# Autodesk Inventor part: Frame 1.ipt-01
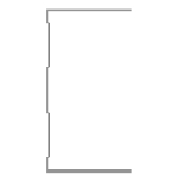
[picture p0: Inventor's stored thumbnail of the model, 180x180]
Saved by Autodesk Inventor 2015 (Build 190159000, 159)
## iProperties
Created: 2015-04
Part Number: Frame 1.ipt-01
Material: Aluminum 6061
Description: Kévin Novo
Document SubType Name: Modeling
Standard: Kevin
Designer: suporte
Standards Organization: Kevin
Language: en-US
Size Designation: (Unnamed 1)
Categories: <MemberInstance><Categories><Category DisplayName="Structural Shapes" InternalName="089c4875-fa83-4c05-b084-43b9cc11f5ed" Mnemonic="GRDR"><CategoryParameter Dis
Density: 2.7 g/cm^3
Appearance: Aluminum - Flat
IsCustomPart: 1
_CCFamilyMember: 1
_CCFamilyDisplayName: Kévin - Kévin Novo
_FrameMemberDoc: Frame Member File
_Version: 15.0.0
_GetPNFromCC: 1
Author: suporte
G_L: 1275,000 mm
G_W: 50,000 mm
G_H: 75,000 mm
+BE02B1BA-F544-4DB9-A8C6-22E0BFEE486C+CUTDETAIL1: Cut
+B7FB69BA-66C3-49F6-BE44-D662183E9D35+CUTDETAIL2: Cut
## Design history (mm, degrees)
node "Start Plane"
node "End Plane"
sketch "Sketch"
  geometry: L1 (24.7, 37.5)-(24.7, 36.9); L2 (24.7, 36.9)-(-24.7, 36.9); L3 (-24.7, -36.9)-(24.7, -36.9); L4 (24.7, -36.9)-(24.7, -37.5); L5 (24.7, -37.5)-(-25.3, -37.5); L6 (-25.3, 37.5)-(24.7, 37.5); L7 (-24.7, 36.9)-(-24.7, 31.9); L8 (-24.7, 31.9)-(-23.3, 30.5); L9 (-23.3, 30.5)-(-23.3, 10.934); L10 (-23.3, 10.934)-(-24.7, 9.534); L11 (-24.7, 9.534)-(-24.7, -9.534); L12 (-24.7, -9.534)-(-23.3, -10.934); L13 (-23.3, -10.934)-(-23.3, -30.5); L14 (-23.3, -30.5)-(-24.7, -31.9); L15 (-24.7, -31.9)-(-24.7, -36.9); L16 (-25.3, -37.5)-(-25.3, -31.651); L17 (-25.3, -31.651)-(-23.9, -30.251); L18 (-23.9, -30.251)-(-23.9, -11.183); L19 (-23.9, -11.183)-(-25.3, -9.783); L20 (-25.3, -9.783)-(-25.3, 9.783); L21 (-25.3, 9.783)-(-23.9, 11.183); L22 (-23.9, 11.183)-(-23.9, 30.251); L23 (-23.9, 30.251)-(-25.3, 31.651); L24 (-25.3, 31.651)-(-25.3, 37.5); L25 (-25.3, 0)-(30.37, 0); 3 further points
  constraints: 50 end point, 10 point on line, 9 parallel, 5 perpendicular, 4 equal length, 3 midpoint, 3 vertical, 2 vertical alignment, 1 collinear, 1 horizontal, 1 horizontal alignment
  dimensions: "d3" = 0.6 distance of L1.start L1.end (= d6); "d5" = 75 distance between parallel lines of L5 L6; "d6" = 0.6 distance between parallel lines of L24 L7 (= d8); "d7" = 0.6 distance between parallel lines of L8 L23 (= d8); "d8" = 0.6 distance between parallel lines of L22 L9 (= d12); "Espessura" = 0.6 distance between parallel lines of L17 L14; "d10" = 0.6 distance between parallel lines of L13 L18 (= Espessura); "d11" = 0.6 distance between parallel lines of L12 L19 (= Espessura); "d12" = 0.6 distance between parallel lines of L21 L10 (= d11); "d13" = 5 distance of L2.end L7.end; "d15" = 135 deg angle of L9 L8; "d16" = 2 distance between parallel lines of L24 L9; "d17" = 50 distance of L6.start L1.start
extrude "Body" join sketch "Sketch" stored distance "d24" = 0.13; taper "d25" = 0 deg
node "Driven Length"
  sketch "Sketch10"
    geometry: L1 (0, 0)-(10, 0) reference
    constraints: 2 end point, 1 horizontal
  workplane "Work Plane7"
  sketch "Sketch11"
    geometry: L1 (-2, -87.5)-(12, -87.5) reference; L2 (-2, 1187.5)-(12, 1187.5) reference
    dimensions: "d27" = 1275 distance between parallel lines of L1 L2 (derived)
workplane "Work Plane8"
split "Split1"
workplane "Work Plane9"
split "Split2"
body "Solid1"
other parameters: "G_OFFSET_START" = 87.5 [user parameter; used in 1 equation term], "G_OFFSET_END" = -12.5 [user parameter; used in 1 equation term], "d22" = -87.5 (= -G_OFFSET_START), "d23" = 1187.5 (= tamanho + G_OFFSET_END), "G_L" = 1275 (= d27) [user parameter], "d34" = 90 deg
